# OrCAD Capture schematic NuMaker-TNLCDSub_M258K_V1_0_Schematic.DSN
size B; title: LCD Connector; rev: v1.1; note: NuMaker-TNLCDSub_M258K V1.0
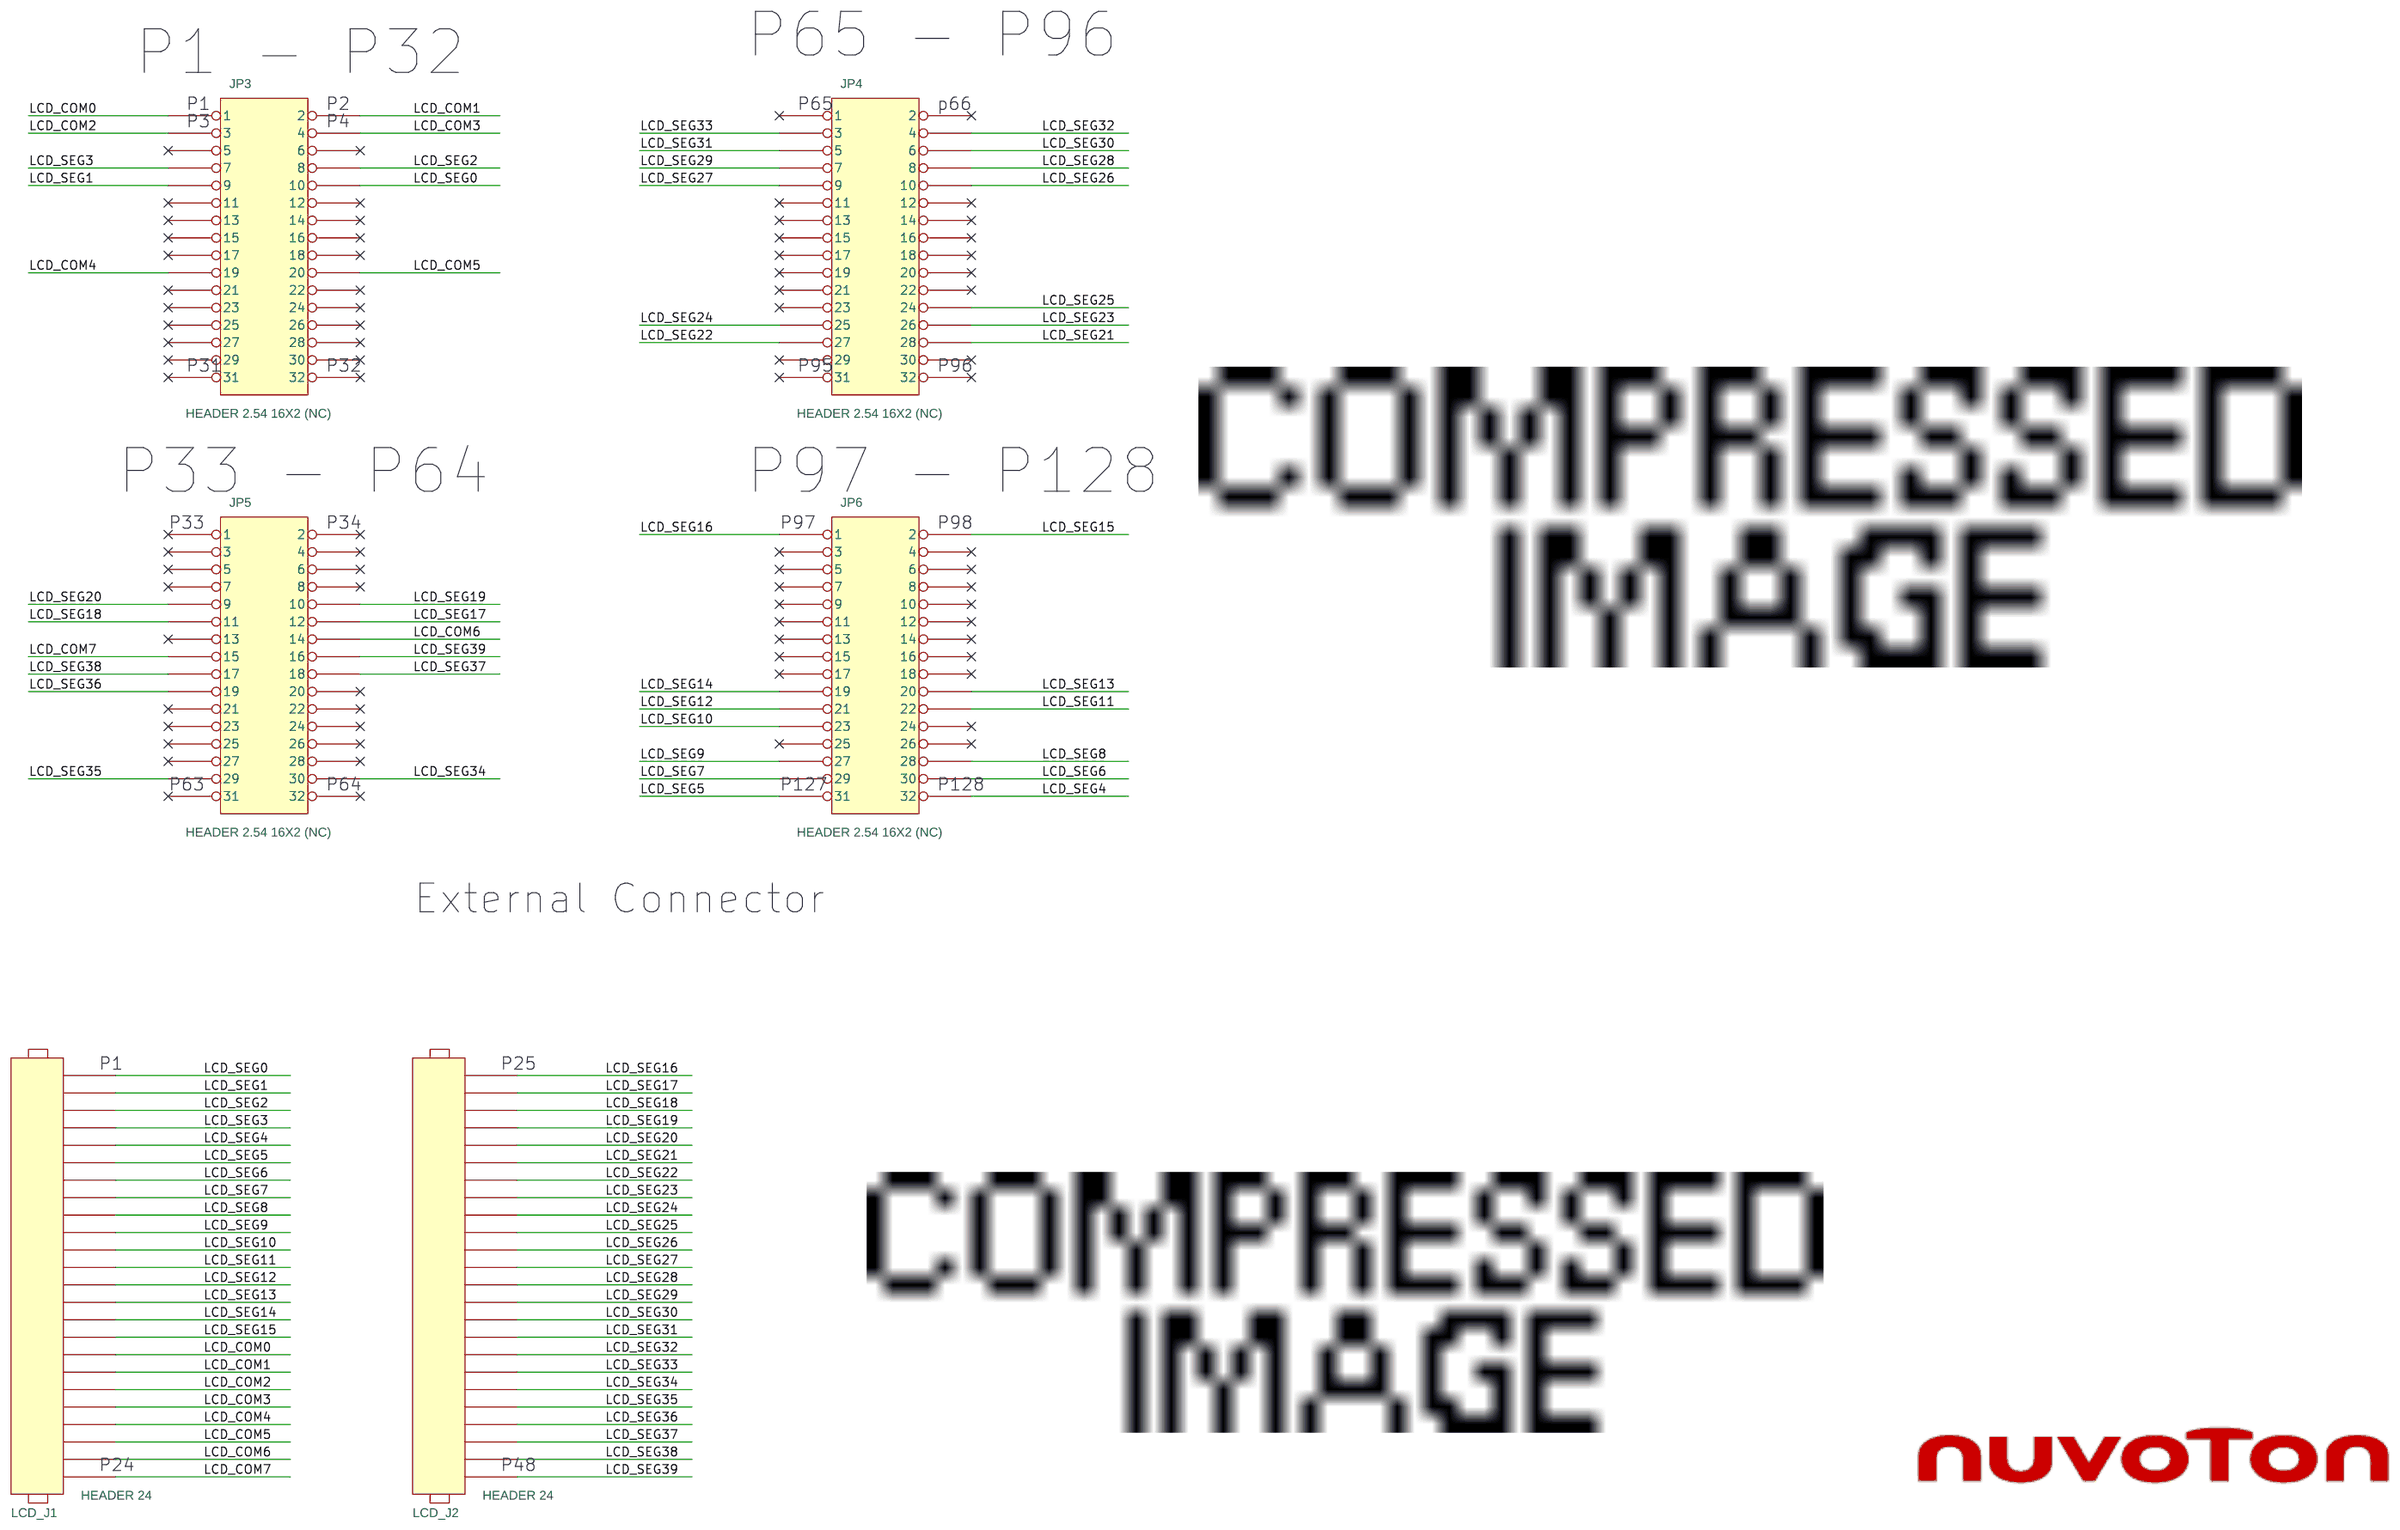
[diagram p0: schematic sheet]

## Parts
JP3  HEADER 2.54 16X2 (NC)  [HEADER16X2]
JP4  HEADER 2.54 16X2 (NC)  [HEADER16X2]
JP5  HEADER 2.54 16X2 (NC)  [HEADER16X2]
JP6  HEADER 2.54 16X2 (NC)  [HEADER16X2]
LCD_J1  HEADER 24  [HEADER24]
LCD_J2  HEADER 24  [HEADER24]

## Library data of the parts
JP3 = HEADER_16X2
JP4 = HEADER_16X2_1
JP5 = HEADER_16X2_2
JP6 = HEADER_16X2_3
LCD_J1 LCD_J2 = HEADER_24

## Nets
LCD_COM0: JP3.1 LCD_J1.17
LCD_COM1: JP3.2 LCD_J1.18
LCD_COM2: JP3.3 LCD_J1.19
LCD_COM3: JP3.4 LCD_J1.20
LCD_COM4: JP3.19 LCD_J1.21
LCD_COM5: JP3.20 LCD_J1.22
LCD_COM6: JP5.14 LCD_J1.23
LCD_COM7: JP5.15 LCD_J1.24
LCD_SEG0: JP3.10 LCD_J1.1
LCD_SEG1: JP3.9 LCD_J1.2
LCD_SEG2: JP3.8 LCD_J1.3
LCD_SEG3: JP3.7 LCD_J1.4
LCD_SEG4: JP6.32 LCD_J1.5
LCD_SEG5: JP6.31 LCD_J1.6
LCD_SEG6: JP6.30 LCD_J1.7
LCD_SEG7: JP6.29 LCD_J1.8
LCD_SEG8: JP6.28 LCD_J1.9
LCD_SEG9: JP6.27 LCD_J1.10
LCD_SEG10: JP6.23 LCD_J1.11
LCD_SEG11: JP6.22 LCD_J1.12
LCD_SEG12: JP6.21 LCD_J1.13
LCD_SEG13: JP6.20 LCD_J1.14
LCD_SEG14: JP6.19 LCD_J1.15
LCD_SEG15: JP6.2 LCD_J1.16
LCD_SEG16: JP6.1 LCD_J2.1
LCD_SEG17: JP5.12 LCD_J2.2
LCD_SEG18: JP5.11 LCD_J2.3
LCD_SEG19: JP5.10 LCD_J2.4
LCD_SEG20: JP5.9 LCD_J2.5
LCD_SEG21: JP4.28 LCD_J2.6
LCD_SEG22: JP4.27 LCD_J2.7
LCD_SEG23: JP4.26 LCD_J2.8
LCD_SEG24: JP4.25 LCD_J2.9
LCD_SEG25: JP4.24 LCD_J2.10
LCD_SEG26: JP4.10 LCD_J2.11
LCD_SEG27: JP4.9 LCD_J2.12
LCD_SEG28: JP4.8 LCD_J2.13
LCD_SEG29: JP4.7 LCD_J2.14
LCD_SEG30: JP4.6 LCD_J2.15
LCD_SEG31: JP4.5 LCD_J2.16
LCD_SEG32: JP4.4 LCD_J2.17
LCD_SEG33: JP4.3 LCD_J2.18
LCD_SEG34: JP5.30 LCD_J2.19
LCD_SEG35: JP5.29 LCD_J2.20
LCD_SEG36: JP5.19 LCD_J2.21
LCD_SEG37: JP5.18 LCD_J2.22
LCD_SEG38: JP5.17 LCD_J2.23
LCD_SEG39: JP5.16 LCD_J2.24

Not connected (* = marked no-connect by the designer): JP3 5* 6* 11* 12* 13* 14* 15* 16* 17* 18* 21* 22* 23* 24* 25* 26* 27* 28* 29* 30* 31* 32*; JP4 1* 2* 11* 12* 13* 14* 15* 16* 17* 18* 19* 20* 21* 22* 23* 29* 30* 31* 32*; JP5 1* 2* 3* 4* 5* 6* 7* 8* 13* 20* 21* 22* 23* 24* 25* 26* 27* 28* 31* 32*; JP6 3* 4* 5* 6* 7* 8* 9* 10* 11* 12* 13* 14* 15* 16* 17* 18* 24* 25* 26*

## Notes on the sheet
- P65 - P96
- P1 - P32
- P1
- P2
- P65
- p66
- P3
- P4
- P31
- P32
- P95
- P96
- P33 - P64
- P97 - P128
- P33
- P34
- P97
- P98
- P63
- P64
- P127
- P128
- External Connector
- P1
- P25
- P24
- P48
